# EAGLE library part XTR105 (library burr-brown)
4-20mA Current Transmitter with Sensor Excitation and Linearization
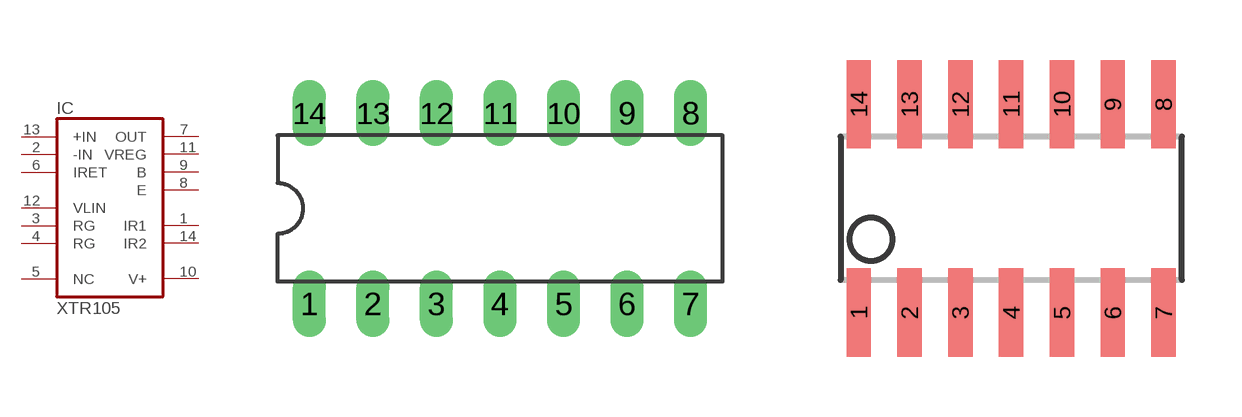
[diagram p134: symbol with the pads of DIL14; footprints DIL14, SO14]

Designator prefix IC

## XTR105P (MF: TEXAS INSTRUMENT CONNECTORS; MPN: XTR105P; OC_FARNELL: 1461141; OC_NEWARK: 77C3629)  [DIL14]
1  IR1  pas
2  -IN  in
3  RG  pas
4  RG  pas
5  NC  nc
6  IRET  in
7  OUT  out
8  E  out
9  B  out
10  V+  pwr
11  VREG  out
12  VLIN  pas
13  +IN  in
14  IR2  pas

## XTR105U (MF: TEXAS INSTRUMENTS; MPN: XTR105U; OC_FARNELL: 1212353; OC_NEWARK: 33C4287)  [SO14]
Pads as for DIL14

## Footprint DIL14 (pad centres in mm)
Dual In Line Package
drill 0.813 long: 1 -7.62,-3.81; 2 -5.08,-3.81; 3 -2.54,-3.81; 4 0,-3.81; 5 2.54,-3.81; 6 5.08,-3.81; 7 7.62,-3.81; 8 7.62,3.81; 9 5.08,3.81; 10 2.54,3.81; 11 0,3.81; 12 -2.54,3.81; 13 -5.08,3.81; 14 -7.62,3.81

## Footprint SO14 (pad centres in mm)
Small Outline Package
smd 0.61 x 2.21: 1 -3.81,-2.603; 2 -2.54,-2.603; 3 -1.27,-2.603; 4 0,-2.603; 5 1.27,-2.603; 6 2.54,-2.603; 7 3.81,-2.603; 8 3.81,2.603; 9 2.54,2.603; 10 1.27,2.603; 11 0,2.603; 12 -1.27,2.603; 13 -2.54,2.603; 14 -3.81,2.603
